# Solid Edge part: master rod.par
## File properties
Author: Vicky Raina
Template: normal.par
Last saved by: Robert a Rhodes jr
Revision: 7
Application: Solid Edge
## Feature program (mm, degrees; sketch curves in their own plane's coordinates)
sketch for "unnamed Protrusion 1" #1 plane through (0, 0, 0) normal (0, 0, 1) x-axis (1, 0, 0)
  circle centre (-104.4884, 26) radius 5
sketch for "unnamed Protrusion 1" #2 plane through (0, 0, 0) normal (0, 0, 1) x-axis (1, 0, 0)
  circle centre (-50.4884, 43) radius 5
sketch for "unnamed Protrusion 1" #3 plane through (0, 0, 0) normal (0, 0, 1) x-axis (1, 0, 0)
  circle centre (-104.4884, -26) radius 5
sketch for "unnamed Protrusion 1" #4 plane through (0, 0, 0) normal (0, 0, 1) x-axis (1, 0, 0)
  circle centre (-50.4884, -43) radius 5
sketch for "unnamed Protrusion 1" #5 plane through (0, 0, 0) normal (0, 0, 1) x-axis (1, 0, 0)
  arc centre (-185.4143, 0) radius 72 from (-116.8653, -22.0235) to (-116.8653, 22.0235) ccw
  arc centre (-104.4884, 26) radius 13 from (-116.8653, 22.0235) to (-104.0399, 38.9923) cw
  arc centre (-101.5558, 110.9494) radius 72 from (-104.0399, 38.9923) to (-58.2987, 53.3923) ccw
  arc centre (-50.4884, 43) radius 13 from (-58.2987, 53.3923) to (-39.1844, 49.4202) cw
  arc centre (23.4225, 84.9783) radius 72 from (-39.1844, 49.4202) to (21.6546, 13) ccw
  line (21.6546, 13) -> (184.5116, 9)
  line (184.5116, 9) -> (184.5116, -9)
  line (184.5116, -9) -> (21.6546, -13)
  arc centre (23.4225, -84.9783) radius 72 from (-39.1844, -49.4202) to (21.6546, -13) cw
  arc centre (-50.4884, -43) radius 13 from (-58.2987, -53.3923) to (-39.1844, -49.4202) ccw
  arc centre (-101.5558, -110.9494) radius 72 from (-104.0399, -38.9923) to (-58.2987, -53.3923) cw
  arc centre (-104.4884, -26) radius 13 from (-116.8653, -22.0235) to (-104.0399, -38.9923) ccw
  dimension (linear) = 104.4884
  dimension (linear) = 104.4884
  dimension (linear) = 21.6546
extrude "unnamed Protrusion 1" add finite 40 symmetric
sketch for "unnamed Protrusion 2" plane through (0, 0, 0) normal (0, 0, 1) x-axis (1, 0, 0)
  circle centre (-65.4884, 0) radius 31.5
extrude "unnamed Protrusion 2" add finite 70 symmetric
sketch for "unnamed Cutout 1" plane through (-65.4884, 0, 35) normal (0, 0, 1) x-axis (1, 0, 0)
  circle centre (0, 0) radius 26
extrude "unnamed Cutout 1" cut through along -normal
sketch for "unnamed Cutout 2" plane through (0, 0, 0) normal (0, 0, 1) x-axis (1, 0, 0)
  arc centre (-185.4143, 0) radius 72 from (-116.8653, -22.0235) to (-116.8653, 22.0235) ccw
  arc centre (-104.4884, 26) radius 13 from (-116.8653, 22.0235) to (-104.0399, 38.9923) cw
  arc centre (-101.5558, 110.9494) radius 72 from (-104.0399, 38.9923) to (-58.2987, 53.3923) ccw
  arc centre (-50.4884, 43) radius 13 from (-58.2987, 53.3923) to (-39.1844, 49.4202) cw
  arc centre (23.4225, 84.9783) radius 72 from (-39.1844, 49.4202) to (21.6408, 13.0003) ccw
  arc centre (26.7635, 219.9485) radius 207.0115 from (21.6408, 13.0003) to (-53.3048, 29.0484) cw
  arc centre (-65.4884, 0) radius 31.5 from (-53.3064, -29.0491) to (-53.3048, 29.0484) cw
  arc centre (26.7787, -220.0192) radius 207.0826 from (21.6337, -13.0005) to (-53.3064, -29.0491) ccw
  arc centre (23.4225, -84.9783) radius 72 from (21.6337, -13.0005) to (-39.1844, -49.4202) ccw
  arc centre (-50.4884, -43) radius 13 from (-39.1844, -49.4202) to (-58.2987, -53.3923) cw
  arc centre (-101.5558, -110.9494) radius 72 from (-58.2987, -53.3923) to (-104.0399, -38.9923) ccw
  arc centre (-104.4884, -26) radius 13 from (-104.0399, -38.9923) to (-116.8653, -22.0235) cw
extrude "unnamed Cutout 2" cut finite 28 symmetric
sketch for "unnamed Cutout 3" plane through (0, 0, 0) normal (0, -1, 0) x-axis (1, 0, 0)
  line (44.7709, 14.1242) -> (184.5116, 9.0608)
  arc centre (52.2023, 91.7693) radius 78 from (21.6546, 20) to (44.7709, 14.1242) ccw
  line (20.7865, 38.9081) -> (21.6546, 20)
  line (184.5116, 38.9081) -> (20.7865, 38.9081)
  line (184.5116, 9.0608) -> (184.5116, 38.9081)
extrude "unnamed Cutout 3" cut finite 355.6 symmetric
mirror "unnamed Mirror 1" of "unnamed Cutout 3" about plane through (0, 0, 0) normal (0, 0, 1)
extrude "unnamed Cutout 4" cut finite 355.6 symmetric
sketch for "unnamed Protrusion 3" plane through (0, 0, 0) normal (0, 0, 1) x-axis (1, 0, 0)
  circle centre (184.5116, 0) radius 17.5
extrude "unnamed Protrusion 3" add finite 42 symmetric
sketch for "unnamed Cutout 5" plane through (184.5116, 0, 21) normal (0, 0, 1) x-axis (1, 0, 0)
  circle centre (0, 0) radius 12
extrude "unnamed Cutout 5" cut through along -normal
sketch for "unnamed Cutout 6" plane through (0, 0, 0) normal (0, 0, 1) x-axis (1, 0, 0)
  line (0.4837, -6) -> (150.4837, -6)
  arc centre (0.4837, 0) radius 6 from (0.4837, 6) to (0.4837, -6) ccw
  line (150.4837, 6) -> (0.4837, 6)
  arc centre (150.4837, 0) radius 6 from (150.4837, 6) to (150.4837, -6) cw
extrude "unnamed Cutout 6" cut finite 222.25 symmetric
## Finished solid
Body 1: solid body, 52 faces, 130 edges, 68 vertices.
  Faces by surface: cylinder 38, plane 14
  Edges by curve: circle 74, line 48, ellipse 8
Bounding box of the edges (mm): 319.500 x 112.000 x 70.000, from (-117.4884, -56, -35) to (202.0116, 56, 35).
Cylindrical faces by radius (mm): R5 x8, R6 x2, R12 x1, R13 x8, R17.5 x1, R26 x1, R31.5 x3, R72 x8, R78 x4, R207.0115 x1, R207.0826 x1
Planar faces by outward normal: +y 1, +z 4, -y 1, -z 4, oblique 4
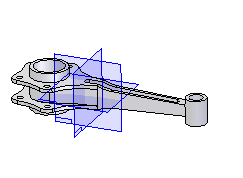
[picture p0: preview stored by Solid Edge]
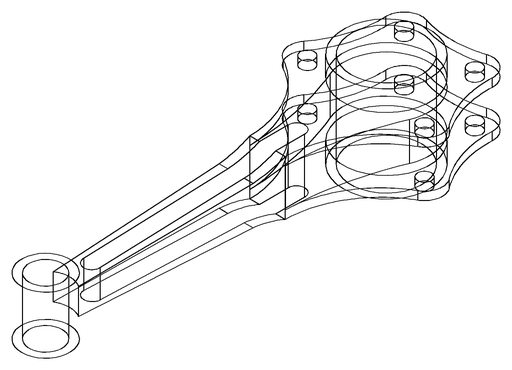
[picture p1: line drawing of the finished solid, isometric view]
